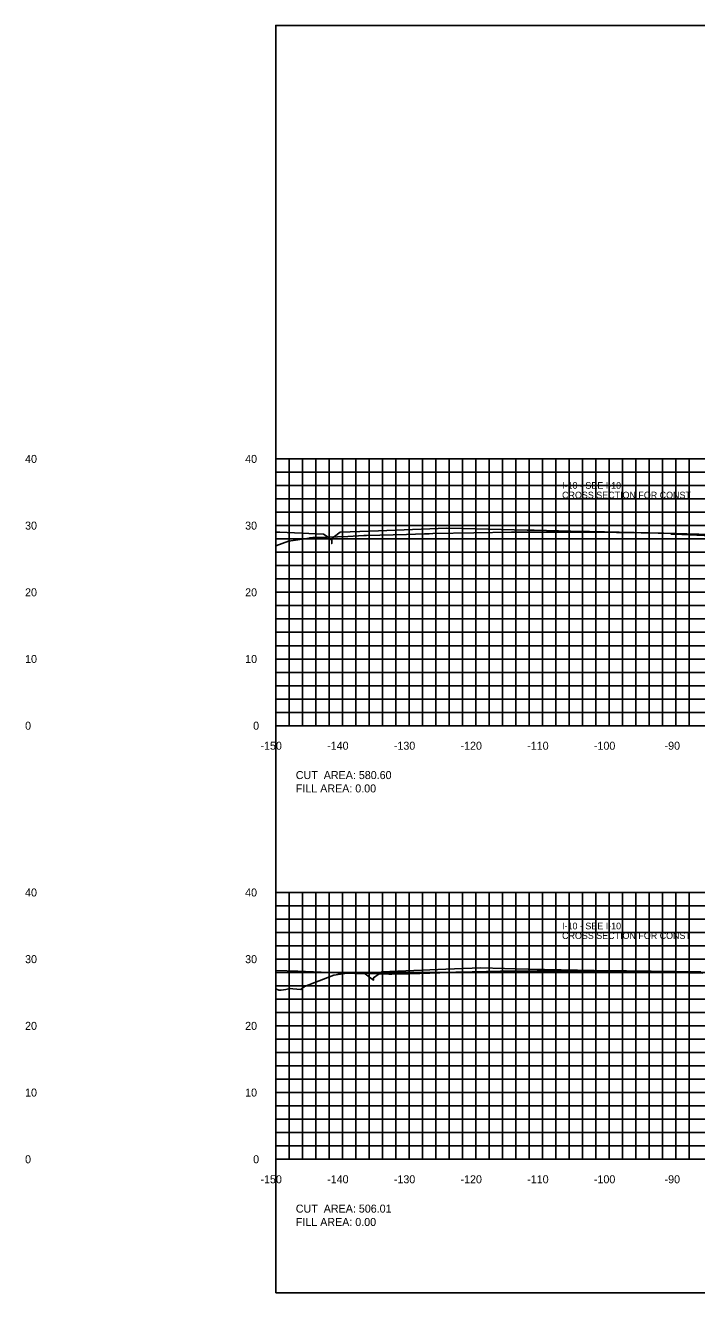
# Model space of a CAD drawing. Extents: x 1800976 to 1805104, y 250057 to 250580.
# Drawn here: x 1803123.4 to 1803224.1, y 250079.4 to 250269.4 of the extents above; entities that cross this region are included whole.
import ezdxf

# ---------------------------------------------------------------- set-up
doc = ezdxf.new("R2010")
doc.units = 0
for name, color, linetype in [('10', 7, 'Continuous'), ('3', 7, 'Continuous'), ('31', 7, 'Continuous'), ('60', 7, 'Continuous'), ('ANNO-TXT', 7, 'Continuous'), ('CL-CNST', 7, 'Continuous'), ('Level 62', 7, 'Continuous'), ('M-ROADS', 7, 'Continuous')]:
    doc.layers.add(name, color=color, linetype=linetype)

msp = doc.modelspace()

# ---------------------------------------------------------------- linework, layer by layer
msp.add_lwpolyline([(1803161, 250079.43), (1803461, 250079.43), (1803461, 250269.43), (1803161, 250269.43)], close=True)
at = {"layer": '60'}
for p, q in [((1803160.94, 250204.43), (1803161, 250204.43)), ((1803161, 250164.43), (1803161, 250204.43)), ((1803160.94, 250194.43), (1803161, 250194.43)), ((1803160.94, 250184.43), (1803161, 250184.43)), ((1803160.94, 250174.43), (1803161, 250174.43)), ((1803160.94, 250164.43), (1803161, 250164.43)), ((1803161, 250164.43), (1803461, 250164.43)), ((1803161, 250164.37), (1803161, 250164.43)), ((1803171, 250164.37), (1803171, 250164.43)), ((1803181, 250164.37), (1803181, 250164.43)), ((1803191, 250164.37), (1803191, 250164.43)), ((1803201, 250164.37), (1803201, 250164.43)), ((1803211, 250164.37), (1803211, 250164.43)), ((1803221, 250164.37), (1803221, 250164.43)), ((1803160.94, 250139.43), (1803161, 250139.43)), ((1803161, 250099.43), (1803161, 250139.43)), ((1803160.94, 250129.43), (1803161, 250129.43)), ((1803160.94, 250119.43), (1803161, 250119.43)), ((1803160.94, 250109.43), (1803161, 250109.43)), ((1803160.94, 250099.43), (1803161, 250099.43)), ((1803161, 250099.43), (1803461, 250099.43)), ((1803161, 250099.37), (1803161, 250099.43)), ((1803171, 250099.37), (1803171, 250099.43)), ((1803181, 250099.37), (1803181, 250099.43)), ((1803191, 250099.37), (1803191, 250099.43)), ((1803201, 250099.37), (1803201, 250099.43)), ((1803211, 250099.37), (1803211, 250099.43)), ((1803221, 250099.37), (1803221, 250099.43))]:
    msp.add_line(p, q, dxfattribs=at)
at = {"layer": 'CL-CNST'}
for points in [[(1803161, 250193.47), (1803161.6, 250193.44), (1803168.14, 250193.17), (1803168.53, 250192.88), (1803169.4, 250192.25), (1803169.4, 250191.74), (1803169.4, 250192.45), (1803169.41, 250192.54), (1803169.79, 250192.82), (1803170.66, 250193.46), (1803175.09, 250193.62), (1803186.64, 250194.06), (1803188.93, 250194.01), (1803198.71, 250193.77), (1803199.73, 250193.75), (1803207.11, 250193.57), (1803208.03, 250193.55), (1803219.2, 250193.29), (1803219.21, 250193.29), (1803220.2, 250193.25), (1803220.2, 250193.24), (1803220.27, 250193.17), (1803220.3, 250193.17), (1803220.73, 250193.15), (1803228.63, 250192.82)], [(1803161, 250127.71), (1803161.07, 250127.71), (1803164.31, 250127.64), (1803171.31, 250127.35), (1803174.4, 250127.22), (1803175.25, 250126.59), (1803175.66, 250126.3), (1803175.66, 250126.41), (1803175.66, 250126.64), (1803176.51, 250127.25), (1803176.92, 250127.55), (1803186.5, 250127.92), (1803191.73, 250128.12), (1803198.85, 250127.95), (1803203.8, 250127.83), (1803208.76, 250127.71), (1803212.95, 250127.62), (1803219.16, 250127.47), (1803225.05, 250127.33)]]:
    msp.add_lwpolyline(points, dxfattribs=at)
at = {"layer": 'Level 62'}
for p, q in [((1803161, 250204.43), (1803461, 250204.43)), ((1803161, 250164.43), (1803161, 250204.43)), ((1803163, 250164.43), (1803163, 250204.43)), ((1803165, 250164.43), (1803165, 250204.43)), ((1803167, 250164.43), (1803167, 250204.43)), ((1803169, 250164.43), (1803169, 250204.43)), ((1803171, 250164.43), (1803171, 250204.43)), ((1803173, 250164.43), (1803173, 250204.43)), ((1803175, 250164.43), (1803175, 250204.43)), ((1803177, 250164.43), (1803177, 250204.43)), ((1803179, 250164.43), (1803179, 250204.43)), ((1803181, 250164.43), (1803181, 250204.43)), ((1803183, 250164.43), (1803183, 250204.43)), ((1803185, 250164.43), (1803185, 250204.43)), ((1803187, 250164.43), (1803187, 250204.43)), ((1803189, 250164.43), (1803189, 250204.43)), ((1803191, 250164.43), (1803191, 250204.43)), ((1803193, 250164.43), (1803193, 250204.43)), ((1803195, 250164.43), (1803195, 250204.43)), ((1803197, 250164.43), (1803197, 250204.43)), ((1803199, 250164.43), (1803199, 250204.43)), ((1803201, 250164.43), (1803201, 250204.43)), ((1803203, 250164.43), (1803203, 250204.43)), ((1803205, 250164.43), (1803205, 250204.43)), ((1803207, 250164.43), (1803207, 250204.43)), ((1803209, 250164.43), (1803209, 250204.43)), ((1803211, 250164.43), (1803211, 250204.43)), ((1803213, 250164.43), (1803213, 250204.43)), ((1803215, 250164.43), (1803215, 250204.43)), ((1803217, 250164.43), (1803217, 250204.43)), ((1803219, 250164.43), (1803219, 250204.43)), ((1803221, 250164.43), (1803221, 250204.43)), ((1803223, 250164.43), (1803223, 250204.43)), ((1803161, 250202.43), (1803461, 250202.43)), ((1803161, 250200.43), (1803461, 250200.43)), ((1803161, 250198.43), (1803461, 250198.43)), ((1803161, 250196.43), (1803461, 250196.43)), ((1803161, 250194.43), (1803461, 250194.43)), ((1803161, 250192.43), (1803461, 250192.43)), ((1803161, 250190.43), (1803461, 250190.43)), ((1803161, 250188.43), (1803461, 250188.43)), ((1803161, 250186.43), (1803461, 250186.43)), ((1803161, 250184.43), (1803461, 250184.43)), ((1803161, 250182.43), (1803461, 250182.43)), ((1803161, 250180.43), (1803461, 250180.43)), ((1803161, 250178.43), (1803461, 250178.43)), ((1803161, 250176.43), (1803461, 250176.43)), ((1803161, 250174.43), (1803461, 250174.43)), ((1803161, 250172.43), (1803461, 250172.43)), ((1803161, 250170.43), (1803461, 250170.43)), ((1803161, 250168.43), (1803461, 250168.43)), ((1803161, 250166.43), (1803461, 250166.43)), ((1803161, 250164.43), (1803461, 250164.43)), ((1803161, 250139.43), (1803461, 250139.43)), ((1803161, 250099.43), (1803161, 250139.43)), ((1803163, 250099.43), (1803163, 250139.43)), ((1803165, 250099.43), (1803165, 250139.43)), ((1803167, 250099.43), (1803167, 250139.43)), ((1803169, 250099.43), (1803169, 250139.43)), ((1803171, 250099.43), (1803171, 250139.43)), ((1803173, 250099.43), (1803173, 250139.43)), ((1803175, 250099.43), (1803175, 250139.43)), ((1803177, 250099.43), (1803177, 250139.43)), ((1803179, 250099.43), (1803179, 250139.43)), ((1803181, 250099.43), (1803181, 250139.43)), ((1803183, 250099.43), (1803183, 250139.43)), ((1803185, 250099.43), (1803185, 250139.43)), ((1803187, 250099.43), (1803187, 250139.43)), ((1803189, 250099.43), (1803189, 250139.43)), ((1803191, 250099.43), (1803191, 250139.43)), ((1803193, 250099.43), (1803193, 250139.43)), ((1803195, 250099.43), (1803195, 250139.43)), ((1803197, 250099.43), (1803197, 250139.43)), ((1803199, 250099.43), (1803199, 250139.43)), ((1803201, 250099.43), (1803201, 250139.43)), ((1803203, 250099.43), (1803203, 250139.43)), ((1803205, 250099.43), (1803205, 250139.43)), ((1803207, 250099.43), (1803207, 250139.43)), ((1803209, 250099.43), (1803209, 250139.43)), ((1803211, 250099.43), (1803211, 250139.43)), ((1803213, 250099.43), (1803213, 250139.43)), ((1803215, 250099.43), (1803215, 250139.43)), ((1803217, 250099.43), (1803217, 250139.43)), ((1803219, 250099.43), (1803219, 250139.43)), ((1803221, 250099.43), (1803221, 250139.43)), ((1803223, 250099.43), (1803223, 250139.43)), ((1803161, 250137.43), (1803461, 250137.43)), ((1803161, 250135.43), (1803461, 250135.43)), ((1803161, 250133.43), (1803461, 250133.43)), ((1803161, 250131.43), (1803461, 250131.43)), ((1803161, 250129.43), (1803461, 250129.43)), ((1803161, 250127.43), (1803461, 250127.43)), ((1803161, 250125.43), (1803461, 250125.43)), ((1803161, 250123.43), (1803461, 250123.43)), ((1803161, 250121.43), (1803461, 250121.43)), ((1803161, 250119.43), (1803461, 250119.43)), ((1803161, 250117.43), (1803461, 250117.43)), ((1803161, 250115.43), (1803461, 250115.43)), ((1803161, 250113.43), (1803461, 250113.43)), ((1803161, 250111.43), (1803461, 250111.43)), ((1803161, 250109.43), (1803461, 250109.43)), ((1803161, 250107.43), (1803461, 250107.43)), ((1803161, 250105.43), (1803461, 250105.43)), ((1803161, 250103.43), (1803461, 250103.43)), ((1803161, 250101.43), (1803461, 250101.43)), ((1803161, 250099.43), (1803461, 250099.43))]:
    msp.add_line(p, q, dxfattribs=at)
at = {"layer": 'M-ROADS'}
for points in [[(1803161, 250191.4), (1803162.9, 250192.09), (1803165.98, 250192.56), (1803166.09, 250192.58), (1803166.55, 250192.64), (1803166.71, 250192.65), (1803167.12, 250192.66), (1803171.82, 250192.8), (1803174.19, 250192.93), (1803174.6, 250192.95), (1803180.58, 250193.12), (1803183.31, 250193.21), (1803184, 250193.22), (1803184.56, 250193.23), (1803190.71, 250193.35), (1803196.33, 250193.44), (1803205.78, 250193.45), (1803208.38, 250193.45), (1803215.77, 250193.33), (1803220.86, 250193.23), (1803226.23, 250193.11)], [(1803161, 250124.98), (1803161.45, 250124.76), (1803161.81, 250124.78), (1803162.49, 250124.89), (1803162.69, 250124.93), (1803163.16, 250125.05), (1803163.55, 250124.99), (1803164.74, 250124.86), (1803165.29, 250125.34), (1803169.68, 250127.03), (1803172.02, 250127.38), (1803177.97, 250127.19), (1803178.4, 250127.16), (1803181.1, 250127.25), (1803187.11, 250127.44), (1803188.01, 250127.46), (1803188.36, 250127.47), (1803194.67, 250127.61), (1803200.18, 250127.69), (1803203.69, 250127.69), (1803212.19, 250127.69), (1803213.6, 250127.67), (1803224.73, 250127.51)]]:
    msp.add_lwpolyline(points, dxfattribs=at)

# ---------------------------------------------------------------- texts
at = {"layer": '10'}
for s, p in [('-150', (1803158.7, 250160.83)), ('-140', (1803168.7, 250160.83)), ('-130', (1803178.7, 250160.83)), ('-120', (1803188.7, 250160.83)), ('-110', (1803198.7, 250160.83)), ('-100', (1803208.7, 250160.83)), ('-90', (1803219.3, 250160.83)), ('-150', (1803158.7, 250095.83)), ('-140', (1803168.7, 250095.83)), ('-130', (1803178.7, 250095.83)), ('-120', (1803188.7, 250095.83)), ('-110', (1803198.7, 250095.83)), ('-100', (1803208.7, 250095.83)), ('-90', (1803219.3, 250095.83))]:
    msp.add_text(s, height=1.2, dxfattribs=at).set_placement(p)
at = {"layer": '3'}
for s, p in [('I-10 - SEE I-10 ', (1803203.93, 250199.95)), ('CROSS SECTION FOR CONST ', (1803203.93, 250198.51)), ('CROSS SECTION FOR CONST ', (1803203.93, 250132.46)), ('I-10 - SEE I-10 ', (1803203.93, 250133.9))]:
    msp.add_text(s, height=1, dxfattribs=at).set_placement(p)
at = {"layer": '31'}
for s, p in [('40', (1803123.4, 250203.83)), ('40', (1803156.4, 250203.83)), ('30', (1803123.4, 250193.83)), ('30', (1803156.4, 250193.83)), ('20', (1803123.4, 250183.83)), ('20', (1803156.4, 250183.83)), ('10', (1803123.4, 250173.83)), ('10', (1803156.4, 250173.83)), ('0', (1803123.4, 250163.83)), ('0', (1803157.6, 250163.83)), ('40', (1803123.4, 250138.83)), ('40', (1803156.4, 250138.83)), ('30', (1803123.4, 250128.83)), ('30', (1803156.4, 250128.83)), ('20', (1803123.4, 250118.83)), ('20', (1803156.4, 250118.83)), ('10', (1803123.4, 250108.83)), ('10', (1803156.4, 250108.83)), ('0', (1803123.4, 250098.83)), ('0', (1803157.6, 250098.83))]:
    msp.add_text(s, height=1.2, dxfattribs=at).set_placement(p)
at = {"layer": '60'}
for p in [(1803161, 250164.43), (1803161, 250099.43)]:
    msp.add_text('-', height=0.0001, dxfattribs=at).set_placement(p)
at = {"layer": 'ANNO-TXT'}
for s, p in [('CUT  AREA: 580.60', (1803164, 250156.43)), ('FILL AREA: 0.00', (1803164, 250154.43)), ('CUT  AREA: 506.01', (1803164, 250091.43)), ('FILL AREA: 0.00', (1803164, 250089.43))]:
    msp.add_text(s, height=1.2, dxfattribs=at).set_placement(p)

doc.saveas('drawing.dxf')
